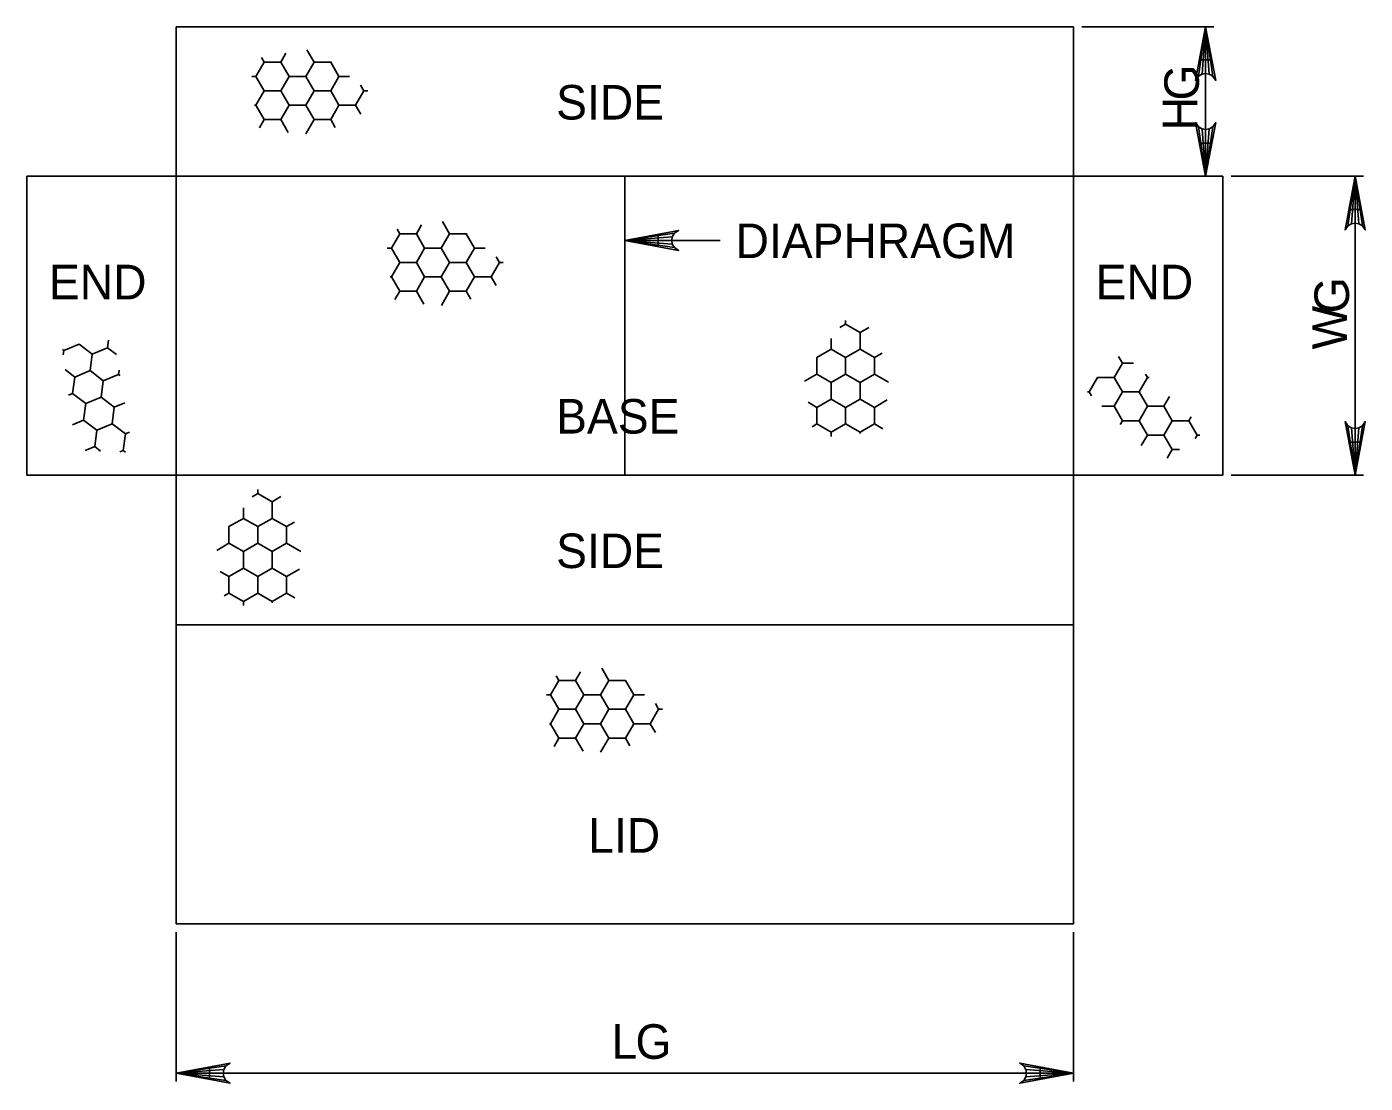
# Model space of a CAD drawing. Extents: x 0 to 36.3, y -44 to 0.
# Drawn here: x 11.306 to 15.952, y -38.248 to -34.581 of the extents above; entities that cross this region are included whole.
import ezdxf

# ---------------------------------------------------------------- set-up
doc = ezdxf.new("R2010")
doc.units = 0
doc.layers.add('3', color=7, linetype='Continuous')
doc.layers.add('5', color=7, linetype='Continuous')

msp = doc.modelspace()

# ---------------------------------------------------------------- linework, layer by layer
at = {"layer": '3'}
for p, q in [((11.8248, -34.5808), (11.8248, -37.6951)), ((14.939, -34.5808), (11.8248, -34.5808)), ((14.939, -37.6951), (14.939, -34.5808)), ((12.1012, -34.7533), (12.13, -34.7033)), ((12.13, -34.7033), (12.1207, -34.6871)), ((12.13, -34.7033), (12.1877, -34.7033)), ((12.1877, -34.7033), (12.2052, -34.673)), ((12.2165, -34.7533), (12.1877, -34.7033)), ((12.2742, -34.7533), (12.303, -34.7033)), ((12.303, -34.7033), (12.2785, -34.6608)), ((12.303, -34.7033), (12.3607, -34.7033)), ((12.3607, -34.7033), (12.3616, -34.7017)), ((12.3895, -34.7533), (12.3607, -34.7033)), ((12.0869, -34.7533), (12.1012, -34.7533)), ((12.13, -34.8032), (12.1012, -34.7533)), ((12.1877, -34.8032), (12.2165, -34.7533)), ((12.2165, -34.7533), (12.2742, -34.7533)), ((12.303, -34.8032), (12.2742, -34.7533)), ((12.3607, -34.8032), (12.3895, -34.7533)), ((12.3895, -34.7533), (12.4265, -34.7533)), ((12.4761, -34.8032), (12.4647, -34.7835)), ((12.1012, -34.8532), (12.13, -34.8032)), ((12.13, -34.8032), (12.1877, -34.8032)), ((12.2165, -34.8532), (12.1877, -34.8032)), ((12.2742, -34.8532), (12.303, -34.8032)), ((12.303, -34.8032), (12.3607, -34.8032)), ((12.3895, -34.8532), (12.3607, -34.8032)), ((12.4472, -34.8532), (12.4761, -34.8032)), ((12.4761, -34.8032), (12.4895, -34.8032)), ((12.0968, -34.8532), (12.1012, -34.8532)), ((12.13, -34.9031), (12.1012, -34.8532)), ((12.1877, -34.9031), (12.2165, -34.8532)), ((12.2165, -34.8532), (12.2742, -34.8532)), ((12.303, -34.9031), (12.2742, -34.8532)), ((12.3607, -34.9031), (12.3895, -34.8532)), ((12.3895, -34.8532), (12.4472, -34.8532)), ((12.4648, -34.8837), (12.4472, -34.8532)), ((12.1132, -34.9322), (12.13, -34.9031)), ((12.13, -34.9031), (12.1877, -34.9031)), ((12.2135, -34.9479), (12.1877, -34.9031)), ((12.2746, -34.9524), (12.303, -34.9031)), ((12.303, -34.9031), (12.3607, -34.9031)), ((12.3763, -34.9302), (12.3607, -34.9031)), ((11.3057, -35.0998), (11.3057, -36.1379)), ((11.3057, -35.0998), (15.4581, -35.0998)), ((13.3819, -35.0998), (13.3819, -36.1379)), ((15.4581, -36.1379), (15.4581, -35.0998)), ((12.7734, -35.2992), (12.7488, -35.2567)), ((12.5716, -35.3492), (12.6004, -35.2992)), ((12.6004, -35.2992), (12.591, -35.2829)), ((12.6004, -35.2992), (12.6581, -35.2992)), ((12.6581, -35.2992), (12.6756, -35.2688)), ((12.6869, -35.3492), (12.6581, -35.2992)), ((12.7446, -35.3492), (12.7734, -35.2992)), ((12.7734, -35.2992), (12.8311, -35.2992)), ((12.8311, -35.2992), (12.832, -35.2977)), ((12.8599, -35.3492), (12.8311, -35.2992)), ((12.5573, -35.3492), (12.5716, -35.3492)), ((12.6004, -35.3991), (12.5716, -35.3492)), ((12.6581, -35.3991), (12.6869, -35.3492)), ((12.6869, -35.3492), (12.7446, -35.3492)), ((12.7734, -35.3991), (12.7446, -35.3492)), ((12.8311, -35.3991), (12.8599, -35.3492)), ((12.8599, -35.3492), (12.8969, -35.3492)), ((12.5716, -35.449), (12.6004, -35.3991)), ((12.6004, -35.3991), (12.6581, -35.3991)), ((12.6869, -35.449), (12.6581, -35.3991)), ((12.7446, -35.449), (12.7734, -35.3991)), ((12.7734, -35.3991), (12.8311, -35.3991)), ((12.8599, -35.449), (12.8311, -35.3991)), ((12.9176, -35.449), (12.9464, -35.3991)), ((12.9464, -35.3991), (12.9351, -35.3794)), ((12.9464, -35.3991), (12.9599, -35.3991)), ((12.5672, -35.449), (12.5716, -35.449)), ((12.6004, -35.499), (12.5716, -35.449)), ((12.6581, -35.499), (12.6869, -35.449)), ((12.6869, -35.449), (12.7446, -35.449)), ((12.7734, -35.499), (12.7446, -35.449)), ((12.8311, -35.499), (12.8599, -35.449)), ((12.8599, -35.449), (12.9176, -35.449)), ((12.9352, -35.4795), (12.9176, -35.449)), ((12.5837, -35.528), (12.6004, -35.499)), ((12.6004, -35.499), (12.6581, -35.499)), ((12.6839, -35.5437), (12.6581, -35.499)), ((12.745, -35.5482), (12.7734, -35.499)), ((12.7734, -35.499), (12.8311, -35.499)), ((12.8468, -35.526), (12.8311, -35.499)), ((14.1482, -35.6137), (14.1285, -35.6251)), ((14.1482, -35.6137), (14.1482, -35.6002)), ((14.1982, -35.6426), (14.1482, -35.6137)), ((14.2287, -35.625), (14.1982, -35.6426)), ((11.4339, -35.7045), (11.4871, -35.6824)), ((11.4872, -35.6824), (11.533, -35.7174)), ((11.5862, -35.6953), (11.5897, -35.6688)), ((14.0983, -35.7002), (14.0983, -35.6632)), ((14.1982, -35.7002), (14.1982, -35.6426)), ((11.4294, -35.7011), (11.4339, -35.7045)), ((11.4319, -35.7199), (11.4339, -35.7045)), ((11.5255, -35.7746), (11.533, -35.7174)), ((11.533, -35.7174), (11.5862, -35.6953)), ((11.5862, -35.6953), (11.6171, -35.7189)), ((14.0483, -35.7291), (14.0468, -35.7282)), ((14.0983, -35.7002), (14.0483, -35.7291)), ((14.1482, -35.7291), (14.0983, -35.7002)), ((14.1982, -35.7002), (14.1482, -35.7291)), ((14.2482, -35.7291), (14.1982, -35.7002)), ((14.2752, -35.7135), (14.2482, -35.7291)), ((15.1091, -35.7487), (15.0957, -35.7256)), ((11.4387, -35.7711), (11.4722, -35.7967)), ((11.4722, -35.7967), (11.5255, -35.7746)), ((11.5255, -35.7746), (11.5713, -35.8097)), ((11.6246, -35.7876), (11.6264, -35.7735)), ((14.0483, -35.7867), (14.0483, -35.7291)), ((14.1482, -35.7867), (14.1482, -35.7291)), ((14.2482, -35.7867), (14.2482, -35.7291)), ((15.0802, -35.7987), (15.1091, -35.7487)), ((15.1091, -35.7487), (15.148, -35.7487)), ((11.4648, -35.8539), (11.4722, -35.7967)), ((11.5638, -35.8668), (11.5713, -35.8097)), ((11.5713, -35.8097), (11.6246, -35.7876)), ((11.6246, -35.7876), (11.6294, -35.7912)), ((14.0483, -35.7867), (14.0058, -35.8113)), ((14.0983, -35.8156), (14.0483, -35.7867)), ((14.1482, -35.7867), (14.0983, -35.8156)), ((14.0983, -35.8732), (14.0983, -35.8156)), ((14.1982, -35.8156), (14.1482, -35.7867)), ((14.2482, -35.7867), (14.1982, -35.8156)), ((14.1982, -35.8732), (14.1982, -35.8156)), ((14.2974, -35.8152), (14.2482, -35.7867)), ((14.9938, -35.8486), (15.0225, -35.7987)), ((15.0227, -35.7987), (15.0802, -35.7987)), ((15.1091, -35.8486), (15.0802, -35.7987)), ((15.1667, -35.8486), (15.1956, -35.7987)), ((15.1956, -35.7987), (15.1886, -35.7864)), ((15.1956, -35.7987), (15.2017, -35.7987)), ((11.4505, -35.8599), (11.4648, -35.8539)), ((11.4648, -35.8539), (11.5106, -35.889)), ((11.5106, -35.889), (11.5638, -35.8668)), ((11.5638, -35.8668), (11.6097, -35.9019)), ((14.9881, -35.8486), (14.9938, -35.8486)), ((15.0015, -35.862), (14.9938, -35.8486)), ((15.0802, -35.8985), (15.1091, -35.8486)), ((15.1091, -35.8486), (15.1667, -35.8486)), ((15.1956, -35.8985), (15.1667, -35.8486)), ((15.2532, -35.8985), (15.2728, -35.8648)), ((11.5032, -35.9462), (11.5106, -35.889)), ((11.6022, -35.9591), (11.6097, -35.9019)), ((11.6097, -35.9019), (11.6457, -35.8869)), ((14.0483, -35.9021), (14.018, -35.8846)), ((14.0983, -35.8732), (14.0483, -35.9021)), ((14.0483, -35.9597), (14.0483, -35.9021)), ((14.1482, -35.9021), (14.0983, -35.8732)), ((14.1982, -35.8732), (14.1482, -35.9021)), ((14.1482, -35.9597), (14.1482, -35.9021)), ((14.2482, -35.9021), (14.1982, -35.8732)), ((14.2929, -35.8762), (14.2482, -35.9021)), ((14.2482, -35.9597), (14.2482, -35.9021)), ((15.038, -35.8985), (15.0802, -35.8985)), ((15.1091, -35.9485), (15.0802, -35.8985)), ((15.1667, -35.9485), (15.1956, -35.8985)), ((15.1956, -35.8985), (15.2532, -35.8985)), ((15.2821, -35.9485), (15.2532, -35.8985)), ((11.4642, -35.9624), (11.5032, -35.9462)), ((11.5032, -35.9462), (11.5489, -35.9812)), ((11.5489, -35.9812), (11.6022, -35.9591)), ((11.6022, -35.9591), (11.648, -35.9942)), ((14.0483, -35.9597), (14.0321, -35.9692)), ((14.0983, -35.9886), (14.0483, -35.9597)), ((14.1482, -35.9597), (14.0983, -35.9886)), ((14.1982, -35.9886), (14.1482, -35.9597)), ((14.2482, -35.9597), (14.1982, -35.9886)), ((14.2772, -35.9766), (14.2482, -35.9597)), ((15.1013, -35.9618), (15.1091, -35.9485)), ((15.1091, -35.9485), (15.1667, -35.9485)), ((15.1956, -35.9984), (15.1667, -35.9485)), ((15.2532, -35.9984), (15.2821, -35.9485)), ((15.2821, -35.9485), (15.3397, -35.9485)), ((15.3397, -35.9485), (15.3478, -35.9346)), ((15.3686, -35.9984), (15.3397, -35.9485)), ((11.5415, -36.0384), (11.5489, -35.9812)), ((11.6405, -36.0513), (11.648, -35.9942)), ((11.648, -35.9942), (11.6628, -35.988)), ((14.0983, -36.0028), (14.0983, -35.9886)), ((14.1982, -35.993), (14.1982, -35.9886)), ((15.1745, -36.035), (15.1956, -35.9984)), ((15.1956, -35.9984), (15.2532, -35.9984)), ((15.2821, -36.0483), (15.2532, -35.9984)), ((15.3621, -36.0097), (15.3686, -35.9984)), ((15.3686, -35.9984), (15.3781, -35.9984)), ((11.509, -36.0519), (11.5415, -36.0384)), ((11.5415, -36.0384), (11.5617, -36.0538)), ((11.6285, -36.0563), (11.6405, -36.0513)), ((11.6405, -36.0513), (11.648, -36.0571)), ((15.2645, -36.0788), (15.2821, -36.0483)), ((15.2821, -36.0483), (15.3075, -36.0483)), ((11.3057, -36.1379), (15.4581, -36.1379)), ((12.1077, -36.2009), (12.1077, -36.1874)), ((12.1077, -36.2009), (12.0879, -36.2122)), ((12.1576, -36.2297), (12.1077, -36.2009)), ((12.1881, -36.2121), (12.1576, -36.2297)), ((12.1576, -36.2874), (12.1576, -36.2297)), ((12.0577, -36.2874), (12.0577, -36.2504)), ((12.0077, -36.3162), (12.0062, -36.3153)), ((12.0577, -36.2874), (12.0077, -36.3162)), ((12.0077, -36.3739), (12.0077, -36.3162)), ((12.1077, -36.3162), (12.0577, -36.2874)), ((12.1576, -36.2874), (12.1077, -36.3162)), ((12.1077, -36.3739), (12.1077, -36.3162)), ((12.2075, -36.3162), (12.1576, -36.2874)), ((12.2346, -36.3006), (12.2075, -36.3162)), ((12.2075, -36.3739), (12.2075, -36.3162)), ((12.0077, -36.3739), (11.9652, -36.3985)), ((12.0577, -36.4027), (12.0077, -36.3739)), ((12.1077, -36.3739), (12.0577, -36.4027)), ((12.1576, -36.4027), (12.1077, -36.3739)), ((12.2075, -36.3739), (12.1576, -36.4027)), ((12.2568, -36.4023), (12.2075, -36.3739)), ((12.0577, -36.4604), (12.0577, -36.4027)), ((12.1576, -36.4604), (12.1576, -36.4027)), ((12.0077, -36.4892), (11.9774, -36.4718)), ((12.0577, -36.4604), (12.0077, -36.4892)), ((12.1077, -36.4892), (12.0577, -36.4604)), ((12.1576, -36.4604), (12.1077, -36.4892)), ((12.2075, -36.4892), (12.1576, -36.4604)), ((12.2523, -36.4634), (12.2075, -36.4892)), ((12.0077, -36.5469), (12.0077, -36.4892)), ((12.1077, -36.5469), (12.1077, -36.4892)), ((12.2075, -36.5469), (12.2075, -36.4892)), ((12.0077, -36.5469), (11.9915, -36.5563)), ((12.0577, -36.5757), (12.0077, -36.5469)), ((12.1077, -36.5469), (12.0577, -36.5757)), ((12.1576, -36.5757), (12.1077, -36.5469)), ((12.2075, -36.5469), (12.1576, -36.5757)), ((12.2366, -36.5637), (12.2075, -36.5469)), ((12.0577, -36.59), (12.0577, -36.5757)), ((12.1576, -36.5802), (12.1576, -36.5757)), ((11.8248, -36.657), (14.939, -36.657)), ((13.1531, -36.8505), (13.1437, -36.8342)), ((13.2107, -36.8505), (13.2282, -36.8202)), ((13.3261, -36.8505), (13.3015, -36.808)), ((13.1242, -36.9004), (13.1531, -36.8505)), ((13.1531, -36.8505), (13.2107, -36.8505)), ((13.2396, -36.9004), (13.2107, -36.8505)), ((13.2973, -36.9004), (13.3261, -36.8505)), ((13.3261, -36.8505), (13.3837, -36.8505)), ((13.3837, -36.8505), (13.3847, -36.849)), ((13.4126, -36.9004), (13.3837, -36.8505)), ((13.11, -36.9004), (13.1242, -36.9004)), ((13.1531, -36.9504), (13.1242, -36.9004)), ((13.2107, -36.9504), (13.2396, -36.9004)), ((13.2396, -36.9004), (13.2973, -36.9004)), ((13.3261, -36.9504), (13.2973, -36.9004)), ((13.3837, -36.9504), (13.4126, -36.9004)), ((13.4126, -36.9004), (13.4496, -36.9004)), ((13.4991, -36.9504), (13.4877, -36.9307)), ((13.1242, -37.0003), (13.1531, -36.9504)), ((13.1531, -36.9504), (13.2107, -36.9504)), ((13.2396, -37.0003), (13.2107, -36.9504)), ((13.2973, -37.0003), (13.3261, -36.9504)), ((13.3261, -36.9504), (13.3837, -36.9504)), ((13.4126, -37.0003), (13.3837, -36.9504)), ((13.4703, -37.0003), (13.4991, -36.9504)), ((13.4991, -36.9504), (13.5125, -36.9504)), ((13.1198, -37.0003), (13.1242, -37.0003)), ((13.1531, -37.0503), (13.1242, -37.0003)), ((13.2107, -37.0503), (13.2396, -37.0003)), ((13.2396, -37.0003), (13.2973, -37.0003)), ((13.3261, -37.0503), (13.2973, -37.0003)), ((13.3837, -37.0503), (13.4126, -37.0003)), ((13.4126, -37.0003), (13.4703, -37.0003)), ((13.4878, -37.0308), (13.4703, -37.0003)), ((13.1363, -37.0793), (13.1531, -37.0503)), ((13.1531, -37.0503), (13.2107, -37.0503)), ((13.2366, -37.0951), (13.2107, -37.0503)), ((13.2976, -37.0996), (13.3261, -37.0503)), ((13.3261, -37.0503), (13.3837, -37.0503)), ((13.3993, -37.0773), (13.3837, -37.0503)), ((11.8248, -37.6951), (14.939, -37.6951))]:
    msp.add_line(p, q, dxfattribs=at)
at = {"layer": '5'}
for p, q in [((14.9678, -34.5808), (15.4268, -34.5808)), ((15.3979, -34.5808), (15.3979, -35.0998)), ((15.4869, -35.0998), (15.9458, -35.0998)), ((15.917, -35.0998), (15.917, -36.1379)), ((13.3819, -35.3225), (13.7133, -35.3225)), ((15.9458, -36.1379), (15.4869, -36.1379)), ((11.8248, -37.7239), (11.8248, -38.2423)), ((14.939, -38.2423), (14.939, -37.7239)), ((11.8248, -38.2135), (14.939, -38.2135))]:
    msp.add_line(p, q, dxfattribs=at)
for points in [[(15.3979, -34.5808), (15.4328, -34.7672), (15.4229, -34.7529), (15.4104, -34.7455), (15.3979, -34.7433), (15.3854, -34.7455), (15.3729, -34.7529), (15.363, -34.7672), (15.3979, -34.5808), (15.3729, -34.7529), (15.3854, -34.7455), (15.3979, -34.5808), (15.3979, -34.7433), (15.4104, -34.7455), (15.3979, -34.5808), (15.4229, -34.7529)], [(15.3979, -35.0998), (15.363, -34.9134), (15.3729, -34.9277), (15.3854, -34.9352), (15.3979, -34.9373), (15.4104, -34.9352), (15.4229, -34.9277), (15.4328, -34.9134), (15.3979, -35.0998), (15.4229, -34.9277), (15.4104, -34.9352), (15.3979, -35.0998), (15.3979, -34.9373), (15.3854, -34.9352), (15.3979, -35.0998), (15.3729, -34.9277)], [(15.917, -35.0998), (15.9519, -35.2862), (15.942, -35.2719), (15.9295, -35.2645), (15.917, -35.2623), (15.9045, -35.2645), (15.892, -35.2719), (15.8821, -35.2862), (15.917, -35.0998), (15.892, -35.2719), (15.9045, -35.2645), (15.917, -35.0998), (15.917, -35.2623), (15.9295, -35.2645), (15.917, -35.0998), (15.942, -35.2719)], [(13.3819, -35.3225), (13.5683, -35.2876), (13.554, -35.2975), (13.5466, -35.31), (13.5444, -35.3225), (13.5466, -35.335), (13.554, -35.3475), (13.5683, -35.3574), (13.3819, -35.3225), (13.554, -35.3475), (13.5466, -35.335), (13.3819, -35.3225), (13.5444, -35.3225), (13.5466, -35.31), (13.3819, -35.3225), (13.554, -35.2975)], [(15.917, -36.1379), (15.8821, -35.9515), (15.892, -35.9658), (15.9045, -35.9733), (15.917, -35.9754), (15.9295, -35.9733), (15.942, -35.9658), (15.9519, -35.9515), (15.917, -36.1379), (15.942, -35.9658), (15.9295, -35.9733), (15.917, -36.1379), (15.917, -35.9754), (15.9045, -35.9733), (15.917, -36.1379), (15.892, -35.9658)], [(11.8248, -38.2135), (12.0113, -38.1786), (11.9969, -38.1885), (11.9895, -38.201), (11.9873, -38.2135), (11.9895, -38.226), (11.9969, -38.2385), (12.0113, -38.2484), (11.8248, -38.2135), (11.9969, -38.2385), (11.9895, -38.226), (11.8248, -38.2135), (11.9873, -38.2135), (11.9895, -38.201), (11.8248, -38.2135), (11.9969, -38.1885)], [(14.939, -38.2135), (14.7526, -38.2484), (14.7669, -38.2385), (14.7743, -38.226), (14.7765, -38.2135), (14.7743, -38.201), (14.7669, -38.1885), (14.7526, -38.1786), (14.939, -38.2135), (14.7669, -38.1885), (14.7743, -38.201), (14.939, -38.2135), (14.7765, -38.2135), (14.7743, -38.226), (14.939, -38.2135), (14.7669, -38.2385)]]:
    msp.add_lwpolyline(points, dxfattribs=at)
for points in [[(15.3788, -34.6962), (15.4172, -34.6962), (15.3979, -34.5808)], [(15.3788, -34.9845), (15.4172, -34.9845), (15.3979, -35.0998)], [(15.8978, -35.2152), (15.9362, -35.2152), (15.917, -35.0998)], [(13.4972, -35.3417), (13.4972, -35.3033), (13.3819, -35.3225)], [(15.8978, -36.0226), (15.9362, -36.0226), (15.917, -36.1379)], [(11.9402, -38.2327), (11.9402, -38.1943), (11.8248, -38.2135)], [(14.8237, -38.2327), (14.8237, -38.1943), (14.939, -38.2135)]]:
    msp.add_lwpolyline(points, close=True, dxfattribs=at)

# ---------------------------------------------------------------- texts
for s, p in [('G', (15.3746, -34.8368)), ('H', (15.369, -34.9407)), ('G', (15.8957, -35.5756)), ('W', (15.8881, -35.701))]:
    msp.add_text(s, height=0.12, rotation=90, dxfattribs=at).set_placement(p)
for s, p in [('SIDE', (13.1433, -34.9029)), ('DIAPHRAGM', (13.7661, -35.3839)), ('END', (11.3827, -35.527)), ('END', (15.016, -35.527)), ('BASE', (13.1433, -35.9931)), ('SIDE', (13.1433, -36.46)), ('LID', (13.2547, -37.4481)), ('L', (13.3353, -38.1632)), ('G', (13.4188, -38.1637))]:
    msp.add_text(s, height=0.12, dxfattribs=at).set_placement(p)

doc.saveas('drawing.dxf')
